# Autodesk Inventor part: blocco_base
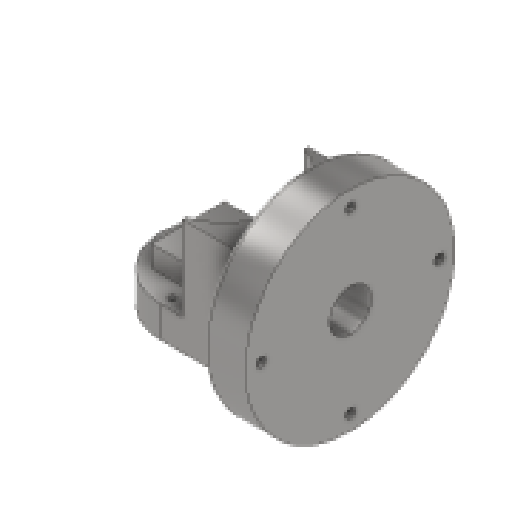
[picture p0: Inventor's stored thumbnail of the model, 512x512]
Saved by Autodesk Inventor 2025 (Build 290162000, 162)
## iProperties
Created: 2025-06
Part Number: blocco_base
Material: Acciaio inossidabile
Document SubType Name: Modeling
Designer: Ryzen5700u
Density: 8 g/cm^3
Appearance: Semilucidato
Author: Ryzen5700u
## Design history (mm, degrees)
sketch "Schizzo1"
  geometry: L1 (17.5, -17.5)-(-17.5, -17.5); L2 (-17.5, -17.5)-(-17.5, 17.5); L3 (-17.5, 17.5)-(17.5, 17.5); L4 (17.5, 17.5)-(17.5, -17.5); L5 (17.5, -17.5)-(-17.5, 17.5); L6 (-17.5, -17.5)-(17.5, 17.5); C1 r 10 at (0, 0); 1 further point
  constraints: 12 end point, 2 midpoint, 2 parallel, 1 centre point, 1 coincident, 1 horizontal, 1 perpendicular
  dimensions: "d0" = 35 distance of L2.end L3.end; "d1" = 35 distance of L1.end L2.end; "d14" = 20 diameter of C1
extrude "Estrusione1" new body sketch "Schizzo1" distance "d2" = 10; taper "d3" = 0 deg
sketch "Schizzo2"
  geometry: C1 r 30 at (0, 0); C2 r 10 at (0, 0); 1 further point
  constraints: 2 centre point, 2 coincident
  dimensions: "d6" = 60 diameter of C1; "d13" = 20 diameter of C2
extrude "Estrusione2" join sketch "Schizzo2" distance "d4" = 15; taper "d5" = 0 deg
sketch "Schizzo3"
  geometry: L1 (-40, -30)-(40, -30); L2 (40, -30)-(40, 30); L3 (40, 30)-(-40, 30); L4 (-40, 30)-(-40, -30); L5 (-40, -30)-(40, 30); L6 (40, -30)-(-40, 30); L7 (0, -30)-(0, 30); C1 r 30 at (0, 0) reference; 3 further points
  constraints: 14 end point, 4 midpoint, 2 parallel, 1 horizontal, 1 perpendicular
  dimensions: "d7" = 80 distance of L3.end L2.end; "d8" = 60 distance of L2.end L1.end
node "Piano di lavoro1"
extrude "Estrusione3" join sketch "Schizzo3" stored distance "d9" = 10; taper "d10" = 0 deg
sketch "Schizzo4"
  geometry: L1 (0, 0)-(0, 55) reference; L2 (60, 55)-(0, 55) reference; C1 r 50 at (30, 27.5); C2 r 15 at (30, 27.5); 1 further point
  constraints: 2 centre point, 1 coincident
  dimensions: "d19" = 100 diameter of C1; "d36" = 30 diameter of C2
extrude "Estrusione4" join sketch "Schizzo4" distance "d11" = 20; taper "d12" = 0 deg
chamfer "Smusso1" distance "d15" = 10; stored, may be unused: second distance "d16" = 2, angle "d17" = 45 deg
fillet "Raccordo2" dims "d20" = 5
sketch "Schizzo5"
  geometry: A1 r 42.5 centre (0, 0) between (-42.5, 0) and (0, 42.5); 3 further points
  constraints: 4 point on circle, 1 centre point
  dimensions: "d21" = 85 diameter of A1
hole "Foro1" sketch "Schizzo5" at (-42.5, 0), (0, 42.5), (42.5, 0), (0, -42.5) diameter "d22" = 4.5; stored, may be unused: countersink angle "d26" = 90 deg, drill point angle "d28" = 0 deg; dims "d23" = 6, "d24" = 8, "d25" = 4.6, "d27" = 50
sketch "Schizzo6"
  geometry: C1 r 3 at (-25, 0) reference; C2 r 3 at (0, 25) reference; C3 r 3 at (0, -25) reference; C4 r 3 at (25, 0) reference; 1 further point
hole "Foro2" sketch "Schizzo6" at (-25, 0), (0, -25), (25, 0), (0, 25) diameter "d29" = 3.4; stored, may be unused: countersink angle "d33" = 90 deg, drill point angle "d35" = 0 deg; dims "d30" = 6, "d31" = 6.5, "d32" = 3.4, "d34" = 50
sketch "Schizzo7"
  geometry: C1 r 50 at (0, 0) reference; 2 further points
  constraints: 1 coincident
hole "Foro3" sketch "Schizzo7" at (0, 0) diameter "d37" = 20; stored, may be unused: countersink angle "d41" = 90 deg, drill point angle "d43" = 0 deg; dims "d38" = 6, "d39" = 6.5, "d40" = 3.4, "d42" = 50
fillet "Raccordo3" dims "d44" = 2
sketch "Schizzo8"
  geometry: L1 (-25, 0)-(-25, 4.178); L2 (-25, 3.233)-(-22.2, 1.617); L3 (-22.2, 1.617)-(-22.2, -1.617); L4 (-22.2, -1.617)-(-25, -3.233); L5 (-25, -3.233)-(-27.8, -1.617); L6 (-27.8, -1.617)-(-27.8, 1.617); L7 (-27.8, 1.617)-(-25, 3.233); C1 r 1.7 at (-25, 0) reference; 2 further points
  constraints: 14 end point, 1 coincident, 1 point on line, 1 vertical, 13 other
  dimensions: "d45" = 5.6 distance between parallel lines of L3 L6
extrude "Estrusione5" cut sketch "Schizzo8" distance "d46" = 3; taper "d47" = 0 deg
pattern_circular "Serie circolare1" dims angle "d49" = 360 deg
node "Solido1"
node "Riferimento1"
node "Riferimento2"
node "Riferimento3"
node "Riferimento4"
